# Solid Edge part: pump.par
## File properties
Author: Mac
Template: Normal.par
Last saved by: Mac
Revision: 3
Application: Solid Edge
Density: 1024,000 kg/m^3
Accuracy: 0,990
Material: ABS Plastic, medium impact
Face Style: Black
Fill Style: ANSI34(Plastic)
Virtual Style: Black (Shiny)
Coef. of Thermal Exp: 5.8e-05
Thermal Conductivity: 2.0
Specific Heat: 0.0
Modulus of Elasticity: 2275269810.0
Poission's Ratio: 0.4
Yield Stress: 43436969.1
Ultimate Stress: 0.0
Elongation: 0.0
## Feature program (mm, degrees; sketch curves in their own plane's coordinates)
sketch for "unnamed Protrusion 1" plane through (0, 0, 0) normal (1, 0, 0) x-axis (0, 1, 0)
  circle centre (0, 0) radius 0.75
extrude "unnamed Protrusion 1" add finite 3 along +normal
sketch for "ExtrudedProtrusion_2" plane through (0.6, 0, 0) normal (-1, 0, 0) x-axis (0, 0, 1)
  line (-0.57, 0.77) -> (0.57, 0.77)
  arc centre (0.57, 0.57) radius 0.2 from (0.57, 0.77) to (0.77, 0.57) cw
  line (0.77, 0.57) -> (0.77, -0.57)
  arc centre (0.57, -0.57) radius 0.2 from (0.77, -0.57) to (0.57, -0.77) cw
  line (0.57, -0.77) -> (-0.57, -0.77)
  arc centre (-0.57, -0.57) radius 0.2 from (-0.57, -0.77) to (-0.77, -0.57) cw
  line (-0.77, -0.57) -> (-0.77, 0.57)
  arc centre (-0.57, 0.57) radius 0.2 from (-0.57, 0.77) to (-0.77, 0.57) ccw
extrude "ExtrudedProtrusion_2" add finite 0.2 along -normal  Profile_Plane1_Distance = 0.6 mm
chamfer "Chamfer_1" setback 0.2
sketch for "ExtrudedProtrusion_3" plane through (0, 0, 0) normal (-1, 0, 0) x-axis (0, -1, 0)
  circle centre (0, 0) radius 0.1
extrude "ExtrudedProtrusion_3" add finite 0.6 along +normal
sketch for "ExtrudedProtrusion_4" plane through (-0.5, 0, 0) normal (-1, 0, 0) x-axis (0, 0, -1)
  line (-0.0863, 0.1495) -> (-0.1726, 0)
  line (-0.1726, 0) -> (-0.0863, -0.1495)
  line (-0.0863, -0.1495) -> (0.0863, -0.1495)
  line (0.0863, -0.1495) -> (0.1726, 0)
  line (0.1726, 0) -> (0.0863, 0.1495)
  line (0.0863, 0.1495) -> (-0.0863, 0.1495)
extrude "ExtrudedProtrusion_4" add finite 0.08 along +normal  Profile_Plane1_Distance = 0.1 mm
sketch for "ExtrudedProtrusion_5" plane through (-0.3798, 0, 0) normal (-1, 0, 0) x-axis (0, -0.866025, -0.5)
extrude "ExtrudedProtrusion_5" add finite 0.06 along -normal  Profile_Plane1_Distance = 0.2002 mm
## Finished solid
Body 1: solid body, 30 faces, 55 edges, 28 vertices.
  Faces by surface: plane 19, cylinder 10, cone 1
  Edges by curve: line 34, circle 21
Bounding box of the edges (mm): 3.600 x 1.540 x 1.540, from (-0.6, -0.77, -0.77) to (3, 0.77, 0.77).
Cylindrical faces by radius (mm): R0.1 x3, R0.2 x4, R0.6021 x1, R0.75 x2
Conical faces (half-angle, radius in mm at the cone's reference point): 45 deg R0.55 x1
Planar faces by outward normal: +x 4, +y 2, +z 1, -x 5, -y 2, -z 1, oblique 4
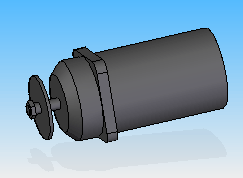
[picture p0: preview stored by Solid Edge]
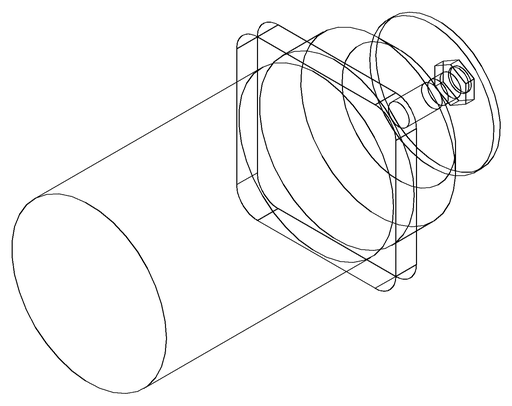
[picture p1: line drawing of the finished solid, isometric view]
